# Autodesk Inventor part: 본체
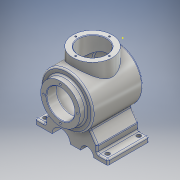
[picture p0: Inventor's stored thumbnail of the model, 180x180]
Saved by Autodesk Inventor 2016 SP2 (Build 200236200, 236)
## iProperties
Created: 2018-08
Part Number: 본체
Material: 알루미늄 6061
Document SubType Name: Modeling
Designer: Administrator
Density: 2.7 g/cm^3
Appearance: 알루미늄 - 평지
Mass: 1907.47 g
Surface Area: 1089.79 cm^2
Volume: 706.47 cm^3
Author: Administrator
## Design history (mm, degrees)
sketch "스케치3"
  geometry: L1 (-108, 50)-(-11.329, 50); L2 (-108, 50)-(-108, 0); L3 (0, 50)-(0, 0); L4 (-108, 0)-(0, 0); L5 (-108, 0)-(0, 0); A1 r 116 centre (-116, 0) between (0, 0) and (-11.329, 50); 1 further point
  constraints: 10 end point, 2 horizontal, 2 point on circle, 2 vertical, 1 centre point, 1 coincident, 1 collinear, 1 point on line
  dimensions: "d6" = 100 diameter of L1 L4; "d7" = 108 distance of L1.start L3.start; "d8" = 116 radius of A1
revolve "회전2" sketch "스케치3" stored, may be unused: angle "d9" = 90 deg
sketch "스케치4"
  geometry: C1 r 38 at (0, 0); 1 further point
  constraints: 1 centre point, 1 coincident
  dimensions: "d10" = 76 diameter of C1
extrude "돌출2" join sketch "스케치4" distance "d11" = 12; taper "d12" = 0 deg
node "작업 평면1"
sketch "스케치5"
  geometry: 1 further point
sketch "스케치6"
  geometry: L1 (-58, 65)-(-20, 65); L2 (-20, 65)-(-20, 17.26); L3 (-20, 17.26)-(-58, 17.26); L4 (-58, 17.26)-(-58, 65); L5 (-108, -50)-(-108, 50) reference; 1 further point
  constraints: 8 end point, 2 parallel, 1 horizontal, 1 perpendicular
  dimensions: "d14" = 65 distance from line of point (0, 0) L1; "d15" = 38 distance of L1.start L1.end; "d16" = 50 distance between parallel lines of L5 L4
revolve "회전3" sketch "스케치6" stored, may be unused: angle "d17" = 90 deg
sketch "스케치7"
  geometry: A1 r 32.5 centre (0, 0) between (0, 32.5) and (32.5, 0); 3 further points
  constraints: 4 point on circle, 1 centre point, 1 coincident
  dimensions: "d18" = 65 diameter of A1
hole "구멍1" sketch "스케치7" at (0, 32.5), (32.5, 0), (0, -32.5), (-32.5, 0) diameter "d19" = 3.242; stored, may be unused: countersink angle "d23" = 90 deg, drill point angle "d25" = 118 deg; dims "d20" = 8, "d21" = 4, "d22" = 2, "d24" = 10
sketch "스케치8"
  geometry: C1 r 38 at (0, -58) reference; C2 r 27 at (0, -58); 1 further point
  constraints: 1 centre point, 1 coincident
  dimensions: "d26" = 54 diameter of C2
extrude "돌출3" cut sketch "스케치8" stored distance "d27" = 12; taper "d28" = 0 deg
sketch "스케치9"
  geometry: L1 (-96, 65)-(-96, 50) reference; L2 (-108, 50)-(-11.329, 50) reference; L3 (-20, 65)-(-20, 50) reference; L4 (-120, 38)-(-120, -38) reference; L5 (-108, 38)-(-120, 38) reference; L6 (-108, -50)-(-108, 50) reference; L7 (-17.837, 40)-(-98, 40); L8 (-98, 40)-(-98, 0); L9 (-98, 0)-(-10, 0); L10 (-101.3, 0)-(31.477, 0); A1 r 116 centre (-116, 0) between (-11.329, -50) and (-11.329, 50) reference; A2 r 106 centre (-116, 0) between (-10, 0) and (-17.837, 40); 1 further point
  constraints: 8 end point, 2 horizontal, 2 point on circle, 1 centre point
  dimensions: "d29" = 10 distance between parallel lines of L2 L7; "d30" = 10 radial gap between concentric circles of A1 A2
revolve "회전4" sketch "스케치9" stored, may be unused: angle "d31" = 90 deg
sketch "스케치10"
  geometry: C1 r 27 at (0, 0); 1 further point
  constraints: 1 centre point, 1 coincident
  dimensions: "d32" = 54 diameter of C1
extrude "돌출4" cut sketch "스케치10" distance "d33" = 50; taper "d34" = 0 deg
sketch "스케치11"
  geometry: A1 r 32.5 centre (0, 0) between (-32.5, 0) and (0, 32.5); 3 further points
  constraints: 4 point on circle, 1 centre point
  dimensions: "d35" = 65 diameter of A1
hole "구멍2" sketch "스케치11" at (-32.5, 0), (0, 32.5), (32.5, 0), (0, -32.5) diameter "d36" = 3.242; stored, may be unused: countersink angle "d40" = 90 deg, drill point angle "d42" = 118 deg; dims "d37" = 8, "d38" = 4, "d39" = 2, "d41" = 10
node "작업 평면3"
  node "작업 평면2"
node "작업 평면4"
node "작업 평면6"
  node "작업 평면5"
node "작업 평면7"
node "작업 평면8"
sketch "스케치13"
  geometry: L1 (-32.416, -79.198)-(-47.039, -100.082); L2 (-47.039, -100.082)-(-47.039, -113.13); L3 (-47.039, -113.13)-(-67.039, -113.13); L4 (-67.039, -113.13)-(-67.039, -123.13); L5 (-67.039, -123.13)-(-40, -123.13); L6 (-15, -123.13)-(5, -123.13); L7 (40, -123.13)-(72.961, -123.13); L8 (72.961, -123.13)-(72.961, -113.13); L9 (72.961, -113.13)-(52.961, -113.13); L10 (52.961, -113.13)-(52.961, -101.151); L11 (52.961, -101.151)-(35.552, -76.288); A1 r 50 centre (0, -41.13) between (-32.416, -79.198) and (35.552, -76.288) reference; A2 r 12.5 centre (-27.5, -123.13) between (-15, -123.13) and (-40, -123.13); A3 r 17.5 centre (22.5, -123.13) between (40, -123.13) and (5, -123.13); 1 further point
  constraints: 22 end point, 6 perpendicular, 6 point on circle, 2 centre point, 2 horizontal, 1 vertical
  dimensions: "d54" = 20 distance of L8.end L9.end; "d55" = 20 distance of L2.end L3.end; "d58" = 82 distance from line of L7 point (0, -41.13); "d59" = 72 vertical distance of point (0, -41.13) L8.end; "d60" = 82 distance from line of point (0, -41.13) L5; "d61" = 72 distance from line of point (0, -41.13) L3; "d62" = 82 distance from line of point (0, -41.13) L6; "d63" = 35 deg angle of L4 L1; "d64" = 35 deg angle of L8 L11; "d65" = 25 diameter of A2; "d66" = 35 diameter of A3; "d67" = 27.5 horizontal distance of point (0, -41.13) A2.centre; "d68" = 22.5 horizontal distance of point (0, -41.13) A3.centre; "d69" = 140 distance of L7.end L4.end; "d93" = 10 distance of L7.end L8.end (derived)
extrude "돌출5" join sketch "스케치13" distance "d70" = 80; taper "d71" = 0 deg
sketch "스케치14"
  geometry: 1 further point
fillet "모깎기1" dims "d72" = 3
chamfer "모따기1" distance "d73" = 1; stored, may be unused: second distance "d74" = 2, angle "d75" = 45 deg
chamfer "모따기2" distance "d76" = 1; stored, may be unused: second distance "d77" = 2, angle "d78" = 45 deg
sketch "스케치16"
  geometry: 1 further point
fillet "모깎기2" dims "d79" = 3
fillet "모깎기3" dims "d80" = 3
fillet "모깎기4" dims "d81" = 3
sketch "스케치17"
  geometry: L1 (7, 67)-(127, 67); L2 (127, 67)-(127, 7); L3 (127, 7)-(7, 7); L4 (7, 7)-(7, 67); L5 (137, 0)-(137, 74) reference; L6 (134, 77)-(120, 77) reference; L7 (120, -3)-(134, -3) reference; L8 (-3, 74)-(-3, 0) reference; 5 further points
  constraints: 8 end point, 4 coincident, 2 parallel, 1 horizontal, 1 perpendicular
  dimensions: "d82" = 10 distance between parallel lines of L5 L2; "d83" = 10 distance between parallel lines of L6 L1; "d84" = 10 distance between parallel lines of L7 L3; "d85" = 10 distance between parallel lines of L8 L4
hole "구멍3" sketch "스케치17" at (7, 67), (7, 7), (127, 7), (127, 67) diameter "d86" = 8; stored, may be unused: countersink angle "d90" = 90 deg, drill point angle "d92" = 118 deg; dims "d87" = 8, "d88" = 4, "d89" = 2, "d91" = 10
node "솔리드2"
other parameters: "d43" = 0, "d44" = -147
